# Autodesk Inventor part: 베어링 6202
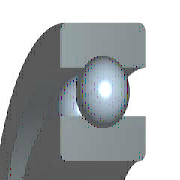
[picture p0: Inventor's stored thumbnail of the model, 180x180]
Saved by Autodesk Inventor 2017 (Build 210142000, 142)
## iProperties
Created: 2012-02
Part Number: 베어링 6202
Material: 강철, 연강
Description: 깊은 그루브 볼 베어링
Document SubType Name: Modeling
Standard: KS B 2023
Designer: mduedu
Standards Organization: KS
Language: ko-KR
Size Designation: 6202 - 15 x 35 x 11
Categories: <MemberInstance><Categories><Category DisplayName="샤프트 부품" InternalName="7f7aeb1f-a693-4053-b835-cee3144e0d98" Mnemonic="SHFT"><Category DisplayName="베어링" Inter
Density: 1 g/cm^3
Appearance: 노란색
IsCustomPart: 1
Author: mduedu
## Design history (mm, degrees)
sketch "스케치" dims "d0" = 5.2 (= -0.26 x WD + 0.26 x BD)
  geometry: L1 (2.9, 12.5)-(8.1, 12.5); L2 (5.5, 12.5)-(5.5, 9.9); L3 (5.5, 12.5)-(5.5, 15.1); L4 (3.568, 10.76)-(0, 10.76); L5 (0, 7.5)-(11, 7.5); L6 (3.568, 14.24)-(0, 14.24); L7 (0, 17.5)-(11, 17.5); L8 (11, 7.5)-(11, 10.76); L9 (7.432, 10.76)-(11, 10.76); L10 (7.432, 14.24)-(11, 14.24); L11 (11, 17.5)-(11, 14.24); L12 (-1.4, 0)-(8.4, 0) reference; L13 (0, -0.3)-(0, 5.3) reference
  constraints: 22 end point, 4 point on line, 2 collinear, 2 perpendicular, 2 symmetric about line, 1 midpoint, 1 parallel, 14 other
  dimensions: "d9" = 15 diameter of L5 L12 (= WD); "d11" = 35 diameter of L7 L12 (= BD); "d12" = 11 distance between parallel lines of L8 L13 (= KB); "d13" = 21.52 diameter of L9 L12 (= 0.326 x BD + 0.674 x WD)
revolve "본체" stored, may be unused: angle "d6" = 90 deg
revolve "볼" stored, may be unused: angle "d7" = 90 deg
pattern_circular "IDS_ARRAYBALL[SIMPL:T]" dims angle "d3" = 360 deg
body "Solid1"
fillet "모깎기1" dims "d1" = 0.6 (= KRS)
other parameters: "WD" = 15 [user parameter; used in 5 equation terms], "BD" = 35 [user parameter; used in 5 equation terms], "KB" = 11 [user parameter; used in 1 equation term], "KRS" = 0.6 [user parameter; used in 1 equation term], "d4" = 0, "d5" = 0, "d8" = 0, "d14" = 0, "d15" = 0, "BBA" = 0 [user parameter], "BC0" = 3750000 [user parameter], "BC" = 7800000 [user parameter], "BR" = 17.5 (= 0.5 x BD) [user parameter], "WR" = 7.5 (= 0.5 x WD) [user parameter]
